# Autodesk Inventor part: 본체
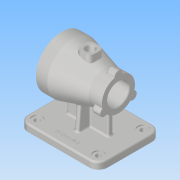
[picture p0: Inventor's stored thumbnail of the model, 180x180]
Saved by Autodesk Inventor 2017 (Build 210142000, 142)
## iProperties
Part Number: 본체
Material: 알루미늄 6061
Document SubType Name: Modeling
Designer: user
Density: 2.7 g/cm^3
Appearance: 알루미늄 - 평지
Mass: 1223.11 g
Surface Area: 899.719 cm^2
Volume: 453.004 cm^3
Author: user
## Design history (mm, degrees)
sketch "스케치1"
  geometry: L1 (54, 55)-(-54, 55); L2 (-70, 39)-(-70, -39); L3 (-54, -55)-(54, -55); L4 (70, -39)-(70, 39); L5 (70, 55)-(-70, -55); L6 (-70, 55)-(70, -55); A1 r 16 centre (54, -39) between (54, -55) and (70, -39); A2 r 16 centre (54, 39) between (70, 39) and (54, 55); A3 r 16 centre (-54, 39) between (-54, 55) and (-70, 39); A4 r 16 centre (-54, -39) between (-70, -39) and (-54, -55); 1 further point
  constraints: 12 end point, 8 point on circle, 8 point on line, 8 tangent, 4 centre point, 3 equal radius, 2 midpoint, 2 parallel, 1 horizontal, 1 perpendicular
  dimensions: "d0" = 140 distance of L6.end L5.end; "d1" = 110 distance of L5.end L6.start; "d2" = 16 radius of A1
extrude "돌출1" new body sketch "스케치1" distance "d3" = 12; taper "d4" = 0 deg
sketch "스케치2"
  geometry: L1 (-84.655, 70)-(96.078, 70); L2 (-54, -12)-(54, -12) reference; L3 (-50, 70)-(-50, 115); L4 (-50, 115)-(-30, 115); L5 (-30, 115)-(27, 99); L6 (27, 99)-(50, 99); L7 (50, 99)-(50, 70); L8 (-70, 0)-(-70, -12) reference; 1 further point
  constraints: 12 end point, 2 perpendicular, 2 point on line, 1 horizontal, 1 parallel, 1 vertical
  dimensions: "d5" = 82 distance between parallel lines of L2 L1; "d6" = 20 distance of L3.end L4.end; "d7" = 100 distance between parallel lines of L7 L3; "d8" = 23 distance of L5.end L6.end; "d9" = 90 diameter of L4 L1; "d10" = 58 diameter of L6 L1; "d11" = 20 distance between parallel lines of L8 L3
revolve "회전1" sketch "스케치2" stored, may be unused: angle "d12" = 90 deg
sketch "스케치3"
  geometry: L1 (50, 41)-(50, 99) reference; L2 (-50, 25)-(-50, 115) reference; L3 (50, 70)-(-50, 70); L4 (-50, 101)-(-30, 101); L5 (-27, 98)-(-27, 98); L6 (-24, 95)-(17, 95); L7 (20, 92)-(20, 92); L8 (23, 89)-(50, 89); L9 (50, 70)-(50, 89); L10 (-50, 101)-(-50, 70); A1 r 3 centre (23, 92) between (20, 92) and (23, 89); A2 r 3 centre (17, 92) between (20, 92) and (17, 95); A3 r 3 centre (-24, 98) between (-27, 98) and (-24, 95); A4 r 3 centre (-30, 98) between (-27, 98) and (-30, 101); 3 further points
  constraints: 16 end point, 8 point on circle, 8 tangent, 6 perpendicular, 6 point on line, 4 centre point, 3 equal radius, 2 midpoint, 1 collinear
  dimensions: "d13" = 38 diameter of L8 L3; "d14" = 50 diameter of L6 L3; "d15" = 62 diameter of L4 L3; "d16" = 23 distance between parallel lines of L5 L2; "d17" = 47 distance of point (-27, 95) point (20, 95); "d18" = 3 radius of A1
revolve "회전2" sketch "스케치3" stored, may be unused: angle "d19" = 90 deg
fillet "모깎기1" dims "d20" = 3
sketch "스케치4"
  geometry: L1 (-37, -4)-(37, -4); L2 (37, -4)-(37, 4); L3 (37, 4)-(-37, 4); L4 (-37, 4)-(-37, -4); L5 (-37, -4)-(37, 4); L6 (37, -4)-(-37, 4); L7 (-4, -24)-(4, -24); L8 (4, -24)-(4, 24); L9 (4, 24)-(-4, 24); L10 (-4, 24)-(-4, -24); L11 (-4, -24)-(4, 24); L12 (4, -24)-(-4, 24); 1 further point
  constraints: 24 end point, 4 midpoint, 4 parallel, 2 horizontal, 2 perpendicular
  dimensions: "d21" = 74 distance of L3.end L2.end; "d22" = 8 distance of L2.end L1.end; "d23" = 8 distance of L9.end L8.end; "d24" = 48 distance of L8.end L7.end
extrude "돌출2" join sketch "스케치4" stored distance "d25" = 0; taper "d26" = 0 deg
node "작업 평면1"
sketch "스케치5"
  geometry: L1 (4.5, 12.5)-(-4.5, 12.5); L2 (-12.5, 4.5)-(-12.5, -4.5); L3 (-4.5, -12.5)-(4.5, -12.5); L4 (12.5, -4.5)-(12.5, 4.5); L5 (12.5, 12.5)-(-12.5, -12.5); L6 (-12.5, 12.5)-(12.5, -12.5); L7 (50, 45)-(50, -45) reference; L8 (-54, -55)-(54, -55) reference; A1 r 8 centre (4.5, -4.5) between (4.5, -12.5) and (12.5, -4.5); A2 r 8 centre (4.5, 4.5) between (12.5, 4.5) and (4.5, 12.5); A3 r 8 centre (-4.5, 4.5) between (-4.5, 12.5) and (-12.5, 4.5); A4 r 8 centre (-4.5, -4.5) between (-12.5, -4.5) and (-4.5, -12.5); 2 further points
  constraints: 12 end point, 8 point on circle, 8 point on line, 8 tangent, 4 centre point, 3 equal radius, 2 midpoint, 2 parallel, 1 horizontal, 1 perpendicular
  dimensions: "d28" = 25 distance of L6.end L5.end; "d29" = 25 distance of L5.end L6.start; "d31" = 50 distance from line of L7 point (0, 0); "d32" = 55 distance from line of point (0, 0) L8; "d33" = 8 radius of A1
extrude "돌출3" join sketch "스케치5" stored distance "d34" = 12; taper "d35" = 0 deg
sketch "스케치6"
  geometry: C1 r 7.5 at (0, 0); 1 further point
  constraints: 1 centre point, 1 coincident
  dimensions: "d36" = 15 diameter of C1
extrude "돌출4" cut sketch "스케치6" stored distance "d37" = 12; taper "d38" = 0 deg
feature "면 기울기1" dims angle "d39" = 5 deg
feature "면 기울기2" dims angle "d40" = 5 deg
fillet "모깎기2" dims "d41" = 3
sketch "스케치7"
  geometry: L1 (0, 0)-(0, 29); L2 (0, 0)-(-25.115, -14.5); L3 (0, 0)-(25.115, -14.5); C1 r 7 at (0, 29); C2 r 7 at (25.115, -14.5); C3 r 7 at (-25.115, -14.5); A1 r 29 centre (0, 0) between (0, 29) and (-25.115, -14.5) reference; 1 further point
  constraints: 6 end point, 3 centre point, 3 coincident, 3 point on circle, 1 vertical
  dimensions: "d42" = 120 deg angle of L3 L1; "d43" = 120 deg angle of L3 L2; "d44" = 14 diameter of C1; "d45" = 14 diameter of C2; "d46" = 14 diameter of C3
extrude "돌출5" join sketch "스케치7" distance "d47" = 15; taper "d48" = 0 deg
fillet "모깎기3" dims "d49" = 3, "d50" = 1
sketch "스케치8" dims "d51" = 80
  geometry: L1 (34.641, -20)-(-34.641, 20); L2 (0, 0)-(40, 0); L3 (-34.641, -20)-(34.641, 20); L4 (0, 0)-(40, 0); L5 (0, -40)-(0, 40); C1 r 45 at (0, 0) reference; 7 further points
  constraints: 10 end point, 5 coincident, 3 midpoint, 2 horizontal, 1 perpendicular, 10 other
  dimensions: "d52" = 150 deg angle of L2 L1; "d53" = 30 deg angle of L4 L3
hole "구멍1" sketch "스케치8" at (0, 40), (34.641, 20), (34.641, -20), (0, -40), (-34.641, -20), (-34.641, 20) diameter "d54" = 3.242; stored, may be unused: countersink angle "d58" = 82 deg, drill point angle "d60" = 118 deg; dims "d55" = 9, "d56" = 3.023, "d57" = 2, "d59" = 11
sketch "스케치9"
  geometry: A1 r 7 centre (25.115, -43.5) between (21.55, -49.524) and (28.549, -37.4) reference; A2 r 7 centre (0, 0) between (7, -0.075) and (-7, -0.075) reference; A3 r 7 centre (-25.115, -43.5) between (-28.549, -37.4) and (-21.55, -49.524) reference; 4 further points
  constraints: 3 coincident
hole "구멍2" sketch "스케치9" at (0, 0), (25.115, -43.5), (-25.115, -43.5) diameter "d61" = 3.242; stored, may be unused: countersink angle "d65" = 82 deg, drill point angle "d67" = 118 deg; dims "d62" = 9, "d63" = 3.023, "d64" = 2, "d66" = 11
chamfer "모따기1" distance "d68" = 1; stored, may be unused: second distance "d69" = 2, angle "d70" = 45 deg
sketch "스케치10"
  geometry: A1 r 13 centre (-54, -39) between (-67, -39) and (-54, -52) reference; A2 r 13 centre (54, -39) between (54, -52) and (67, -39) reference; A3 r 13 centre (54, 39) between (67, 39) and (54, 52) reference; A4 r 13 centre (-54, 39) between (-54, 52) and (-67, 39) reference; 5 further points
  constraints: 4 coincident
hole "구멍3" sketch "스케치10" at (54, 39), (54, -39), (-54, -39), (-54, 39) diameter "d71" = 9; stored, may be unused: countersink angle "d75" = 82 deg, drill point angle "d77" = 118 deg; dims "d72" = 9, "d73" = 18, "d74" = 2, "d76" = 12
sketch "스케치11"
  geometry: L1 (-70, 39)-(-70, -39) reference; L2 (-54, -55)-(54, -55) reference; 2 further points
  constraints: 1 other
  dimensions: "d78" = 70 distance from line of L1 point (0, -40); "d79" = 15 distance from line of L2 point (0, -40)
feature "엠보싱1" sketch "스케치11" dims "d0" = 140, "d1" = 110, "d2" = 16, "d80" = 0.5, "d81" = 0
node "솔리드1"
other parameters: "d27" = -127
